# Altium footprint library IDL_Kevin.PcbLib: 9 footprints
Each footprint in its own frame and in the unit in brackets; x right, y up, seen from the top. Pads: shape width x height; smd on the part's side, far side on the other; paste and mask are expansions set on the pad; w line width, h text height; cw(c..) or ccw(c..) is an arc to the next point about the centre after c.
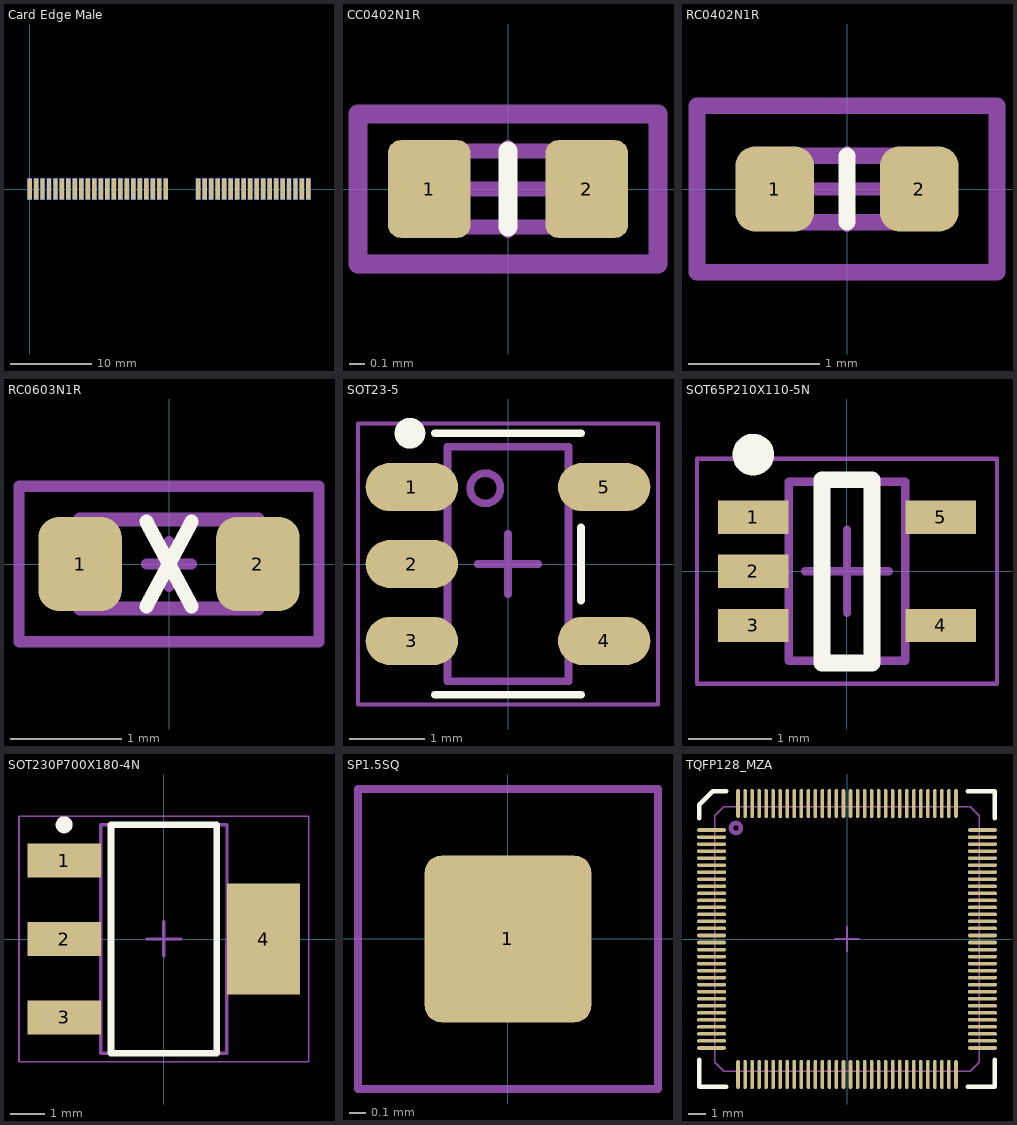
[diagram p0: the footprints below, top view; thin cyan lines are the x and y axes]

## Card Edge Male [mm]
pads (80):
  rect 0.55x2.6 smd: 1(0,0.003) 3(0.8,0.003) 5(1.6,0.003) 7(2.4,0.003) 9(3.2,0.003) 11(4,0.003) 13(4.8,0.003) 15(5.6,0.003) 17(6.4,0.003) 19(7.2,0.003) 21(8,0.003) 23(8.8,0.003) 25(9.6,0.003) 27(10.4,0.003) 29(11.2,0.003) 31(12,0.003) 33(12.8,0.003) 35(13.6,0.003) 37(14.4,0.003) 39(15.2,0.003) 41(16,0.003) 43(16.8,0.003) 45(20.8,0.003) 47(21.6,0.003) 49(22.4,0.003) 51(23.2,0.003) 53(24,0.003) 55(24.8,0.003) 57(25.6,0.003) 59(26.4,0.003) 61(27.2,0.003) 63(28,0.003) 65(28.8,0.003) 67(29.6,0.003) 69(30.4,0.003) 71(31.204,0.003) 73(32,0.003) 75(32.802,0.003) 77(33.598,0.003) 79(34.4,0.003)
  rect 0.55x2.6 smd far side: 2(0,0.003) 4(0.8,0.003) 6(1.6,0.003) 8(2.4,0.003) 10(3.2,0.003) 12(4,0.003) 14(4.8,0.003) 16(5.6,0.003) 18(6.4,0.003) 20(7.2,0.003) 22(8,0.003) 24(8.8,0.003) 26(9.6,0.003) 28(10.4,0.003) 30(11.2,0.003) 32(12,0.003) 34(12.8,0.003) 36(13.6,0.003) 38(14.4,0.003) 40(15.2,0.003) 42(16,0.003) 44(16.8,0.003) 46(20.8,0.003) 48(21.6,0.003) 50(22.4,0.003) 52(23.2,0.003) 54(24,0.003) 56(24.8,0.003) 58(25.6,0.003) 60(26.4,0.003) 62(27.2,0.003) 64(28,0.003) 66(28.8,0.003) 68(29.6,0.003) 70(30.4,0.003) 72(31.2,0.003) 74(32,0.003) 76(32.8,0.003) 78(33.6,0.003) 80(34.4,0.003)

## CC0402N1R [mm] "Chip capacitor 0402 ROUND pad"
height 0.5
pads (2):
  rrect30% 0.55x0.65 smd mask+0.025: 1(-0.525,0) 2(0.525,0)
Top Overlay:
  lines w0.127: 0,-0.254 0,0.254
Mechanical 13:
  lines w0.1: -0.508,-0.254 -0.508,0.254 0.508,0.254 0.508,-0.254 -0.508,-0.254
Mechanical 15:
  lines w0.102: -0.3,0 0.3,0 ; 0,-0.275 0,0.275
  lines w0.127: -1,-0.5 1,-0.5 1,0.5 -1,0.5 -1,-0.5
3D body: height 0.5, standoff 0, extent -0.508,-0.254 -0.3,0.254
3D body: height 0.5, standoff 0, extent 0.3,-0.254 0.508,0.254
3D body: height 0.5, standoff 0, extent -0.3,-0.254 0.3,0.254

## RC0402N1R [mm] "Chip capacitor 0402 ROUNDED PAD"
height 0.5
pads (2):
  rrect50% 0.6x0.65 smd: 1(-0.55,0) 2(0.55,0)
Top Overlay:
  lines w0.127: 0,-0.254 0,0.254
Mechanical 13:
  lines w0.127: -0.508,-0.254 -0.508,0.254 0.508,0.254 0.508,-0.254 -0.508,-0.254
Mechanical 15:
  lines w0.102: -0.3,0 0.3,0 ; 0,-0.275 0,0.275
  lines w0.127: -1.143,-0.635 1.143,-0.635 1.143,0.635 -1.143,0.635 -1.143,-0.635
3D body: height 0.35, standoff 0, extent -0.508,-0.254 0.508,0.254
3D body: height 0.36, standoff 0.35, extent -0.35,-0.254 0.35,0.254

## RC0603N1R [mm] "Chip resistor 0603 ROUNDED PAD"
height 0.45
pads (2):
  rrect50% 0.75x0.85 smd: 1(-0.8,0) 2(0.8,0)
Top Overlay:
  lines w0.127: -0.203,-0.381 0.203,0.381 ; -0.203,0.381 0.203,-0.381
Mechanical 13:
  lines w0.127: -0.8,-0.4 -0.8,0.4 0.8,0.4 0.8,-0.4 -0.8,-0.4
Mechanical 15:
  lines w0.1: -0.2,0 0.2,0 ; 0,-0.2 0,0.2 ; -1.35,-0.7 -1.35,0.7 1.35,0.7 1.35,-0.7 -1.35,-0.7
3D body: height 0.45, standoff 0, extent -0.8,-0.4 0.8,0.4
3D body: height 0.46, standoff 0.45, extent -0.6,-0.4 0.6,0.4

## SOT23-5 [mil]
height 40
pads (5):
  oval 48x25 smd mask+2: 1(-50,40) 2(-50,0) 3(-50,-40) 4(50,-40) 5(50,40)
Top Overlay:
  circle w8: c-51,68 r4
  lines w4: -38,-68 38,-68 ; -38,68 38,68 ; 38,-19 38,19
Mechanical 13:
  circle w3.94: c-11.81,39.37 r7.87
  lines w4: -31.5,-61.02 31.5,-61.02 31.5,61.02 -31.5,61.02 -31.5,-61.02
Mechanical 15:
  lines w2: -78,-73 78,-73 78,73 -78,73 -78,-73
  lines w4: -15.75,0 15.75,0 ; 0,-15.75 0,15.75
3D body: height 11.81, standoff 0, extent 31.5,-48.23 50.2,-30.51
3D body: height 11.81, standoff 0, extent 31.5,30.51 50.2,48.23
3D body: height 11.81, standoff 0, extent -50.2,-8.86 -31.5,8.86
3D body: height 11.81, standoff 0, extent -50.2,-48.23 -31.5,-30.51
3D body: height 11.81, standoff 0, extent -50.2,30.51 -31.5,48.23
3D body: height 57.09, standoff 0, extent -31.5,-61.02 31.5,61.02
3D body: height 57.48, standoff 57.09, extent -19.68,31.5 -3.94,47.24

## SOT65P210X110-5N [mm] "SOT23, 5-Leads, Body 2.00x2.10mm, Pitch 0.65mm, IPC Medium Density"
height 1.1
pads (5):
  rect 0.85x0.4 smd: 1(-1.125,0.65) 2(-1.125,0) 3(-1.125,-0.65) 4(1.125,-0.65) 5(1.125,0.65)
Top Overlay:
  circle w0.25: c-1.125,1.4 r0.125
  lines w0.2: -0.3,-1.1 -0.3,1.1 0.3,1.1 0.3,-1.1 -0.3,-1.1
Mechanical 13:
  lines w0.1: -0.7,-1.075 0.7,-1.075 0.7,1.075 -0.7,1.075 -0.7,-1.075
Mechanical 15:
  lines w0.05: -1.8,-1.35 1.8,-1.35 1.8,1.35 -1.8,1.35 -1.8,-1.35
  lines w0.1: -0.5,0 0.5,0 ; 0,-0.5 0,0.5
3D body: height 1.1, standoff 0.1, extent -0.7,-1.075 0.7,1.075

## SOT230P700X180-4N [mm] "SOT223, 4-Leads, Body 6.50x7.00mm (avg), Pitch 2.30mm, IPC Medium Density"
height 1.8
pads (4):
  rect 2.15x1 smd: 1(-2.925,2.3) 2(-2.925,0) 3(-2.925,-2.3)
  rect 2.15x3.25 smd: 4(2.925,0)
Top Overlay:
  circle w0.25: c-2.925,3.35 r0.125
  lines w0.2: -1.55,-3.35 -1.55,3.35 1.55,3.35 1.55,-3.35 -1.55,-3.35
Mechanical 13:
  lines w0.1: -1.85,-3.35 -1.85,3.35 1.85,3.35 1.85,-3.35 -1.85,-3.35
Mechanical 15:
  lines w0.05: -4.25,-3.6 -4.25,3.6 4.25,3.6 4.25,-3.6 -4.25,-3.6
  lines w0.1: -0.5,0 0.5,0 ; 0,-0.5 0,0.5
3D body: height 1.8, standoff 0.02, extent -1.85,-3.35 1.85,3.35

## SP1.5SQ [mm] "Solder Pad 1.5mm SMT"
height 0.5
pads (1):
  rrect20% 1x1 smd: 1(0,0)
Mechanical 13:
  lines w0.05: -0.9,-0.9 0.9,-0.9 0.9,0.9 -0.9,0.9 -0.9,-0.9

## TQFP128_MZA [mil]
height 47.24
pads (128):
  oval 65x8 smd mask+2: 1(-302.5,243.35) 2(-302.5,227.65) 3(-302.5,211.95) 4(-302.5,196.25) 5(-302.5,180.55) 6(-302.5,164.85) 7(-302.5,149.15) 8(-302.5,133.45) 9(-302.5,117.75) 10(-302.5,102.05) 11(-302.5,86.35) 12(-302.5,70.65) 13(-302.5,54.95) 14(-302.5,39.25) 15(-302.5,23.55) 16(-302.5,7.85) 17(-302.5,-7.85) 18(-302.5,-23.55) 19(-302.5,-39.25) 20(-302.5,-54.95) 21(-302.5,-70.65) 22(-302.5,-86.35) 23(-302.5,-102.05) 24(-302.5,-117.75) 25(-302.5,-133.45) 26(-302.5,-149.15) 27(-302.5,-164.85) 28(-302.5,-180.55) 29(-302.5,-196.25) 30(-302.5,-211.95) 31(-302.5,-227.65) 32(-302.5,-243.35) 65(302.5,-243.35) 66(302.5,-227.65) 67(302.5,-211.95) 68(302.5,-196.25) 69(302.5,-180.55) 70(302.5,-164.85) 71(302.5,-149.15) 72(302.5,-133.45) 73(302.5,-117.75) 74(302.5,-102.05) 75(302.5,-86.35) 76(302.5,-70.65) 77(302.5,-54.95) 78(302.5,-39.25) 79(302.5,-23.55) 80(302.5,-7.85) 81(302.5,7.85) 82(302.5,23.55) 83(302.5,39.25) 84(302.5,54.95) 85(302.5,70.65) 86(302.5,86.35) 87(302.5,102.05) 88(302.5,117.75) 89(302.5,133.45) 90(302.5,149.15) 91(302.5,164.85) 92(302.5,180.55) 93(302.5,196.25) 94(302.5,211.95) 95(302.5,227.65) 96(302.5,243.35)
  oval 8x65 smd mask+2: 33(-243.35,-302.5) 34(-227.65,-302.5) 35(-211.95,-302.5) 36(-196.25,-302.5) 37(-180.55,-302.5) 38(-164.85,-302.5) 39(-149.15,-302.5) 40(-133.45,-302.5) 41(-117.75,-302.5) 42(-102.05,-302.5) 43(-86.35,-302.5) 44(-70.65,-302.5) 45(-54.95,-302.5) 46(-39.25,-302.5) 47(-23.55,-302.5) 48(-7.85,-302.5) 49(7.85,-302.5) 50(23.55,-302.5) 51(39.25,-302.5) 52(54.95,-302.5) 53(70.65,-302.5) 54(86.35,-302.5) 55(102.05,-302.5) 56(117.75,-302.5) 57(133.45,-302.5) 58(149.15,-302.5) 59(164.85,-302.5) 60(180.55,-302.5) 61(196.25,-302.5) 62(211.95,-302.5) 63(227.65,-302.5) 64(243.35,-302.5) 97(243.35,302.5) 98(227.65,302.5) 99(211.95,302.5) 100(196.25,302.5) 101(180.55,302.5) 102(164.85,302.5) 103(149.15,302.5) 104(133.45,302.5) 105(117.75,302.5) 106(102.05,302.5) 107(86.35,302.5) 108(70.65,302.5) 109(54.95,302.5) 110(39.25,302.5) 111(23.55,302.5) 112(7.85,302.5) 113(-7.85,302.5) 114(-23.55,302.5) 115(-39.25,302.5) 116(-54.95,302.5) 117(-70.65,302.5) 118(-86.35,302.5) 119(-102.05,302.5) 120(-117.75,302.5) 121(-133.45,302.5) 122(-149.15,302.5) 123(-164.85,302.5) 124(-180.55,302.5) 125(-196.25,302.5) 126(-211.95,302.5) 127(-227.65,302.5) 128(-243.35,302.5)
Top Overlay:
  lines w10: -330,-270 -330,-330 -270,-330 ; -330,270 -330,300 -300,330 -270,330 ; 270,-330 330,-330 330,-270 ; 270,330 330,330 330,270
Mechanical 13:
  circle w10: c-248.03,248.03 r11.14
  lines w3.94: -295.28,-275.59 -295.28,275.59 -275.59,295.28 275.59,295.28 295.28,275.59 295.28,-275.59 275.59,-295.28 -275.59,-295.28 -295.28,-275.59
Mechanical 15:
  lines w3.94: -27.56,0 27.56,0 ; 0,-27.56 0,27.56
3D body: height 47.64, standoff 47.24, extent -255.81,220.5 -216.59,259.79
3D body: height 47.24, standoff 0, extent -295.28,-295.28 295.28,295.28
